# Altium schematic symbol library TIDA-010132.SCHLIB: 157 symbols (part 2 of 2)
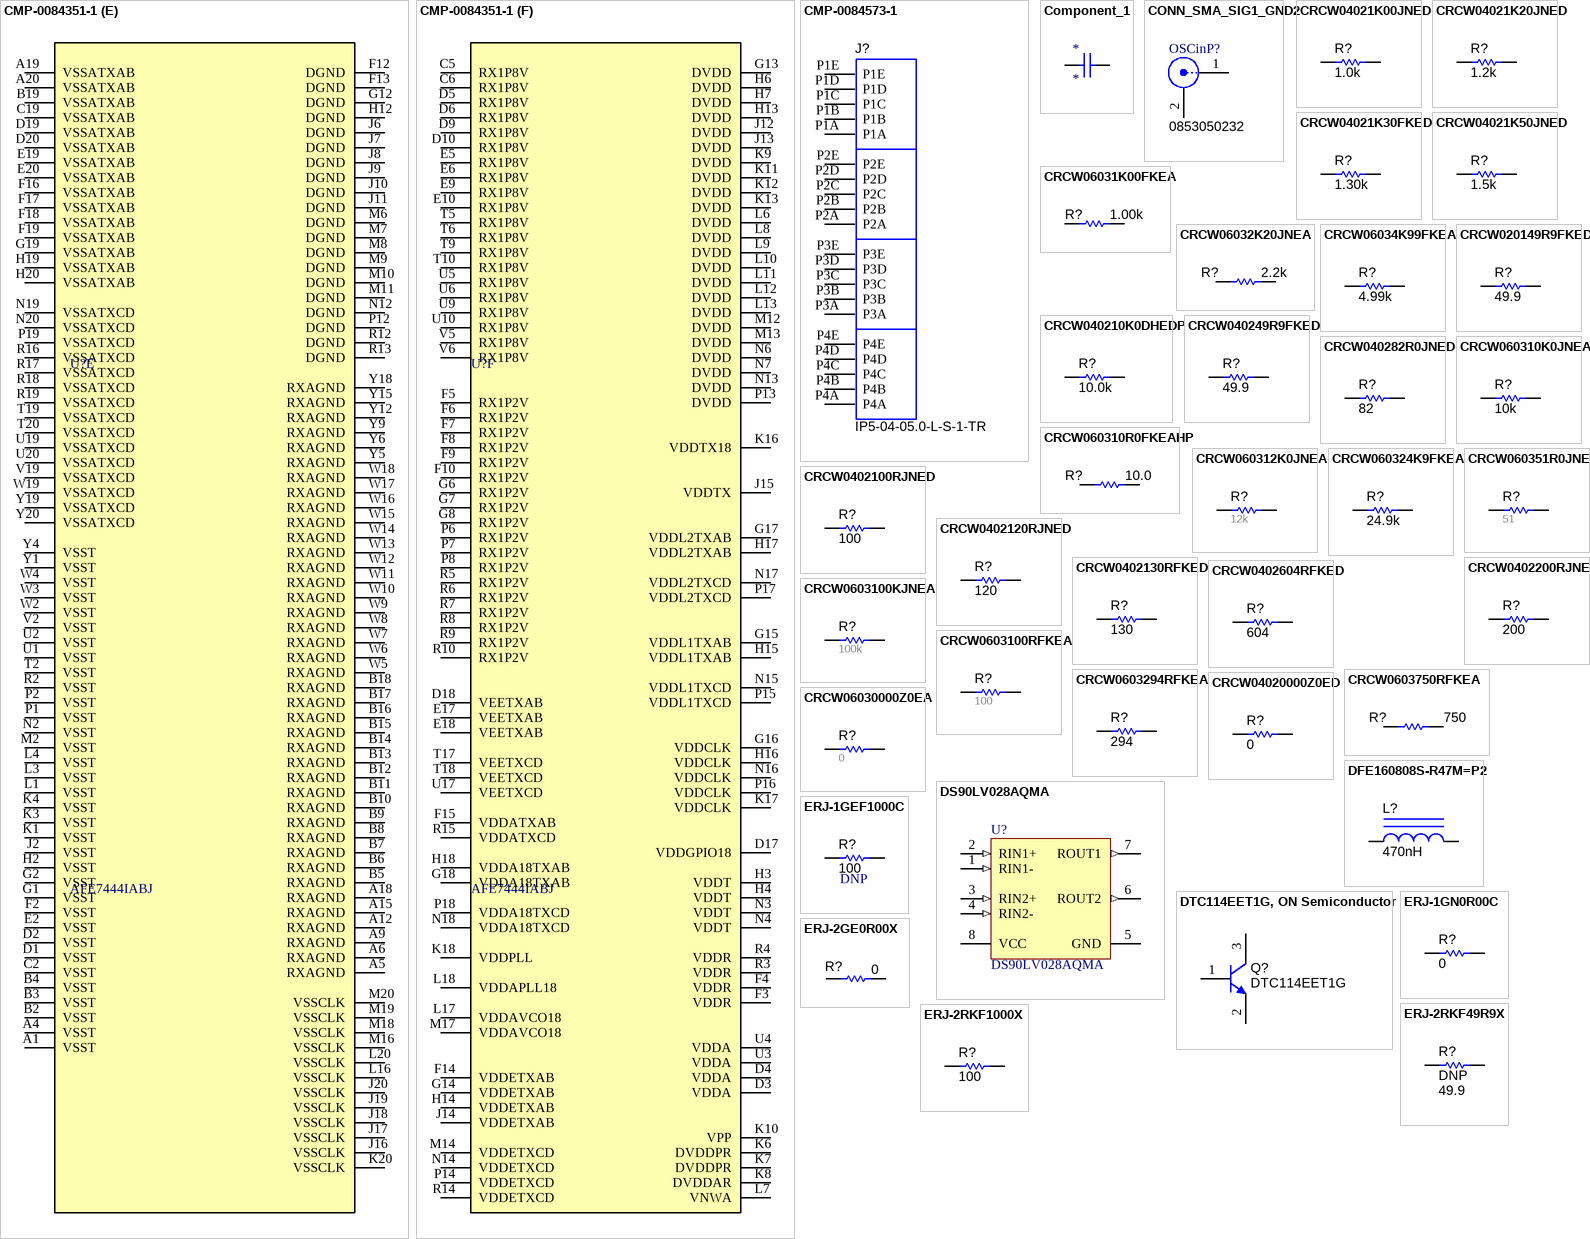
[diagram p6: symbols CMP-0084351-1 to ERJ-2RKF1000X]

## DFE160808S-R47M=P2
designator L?  ValueDisplayed: 470nH  (hidden comment: DFE160808S-R47M=P2)
Inductor, Shielded, Metal Composite, 470 nH, 2.4 A, 0.064 ohm, SMD; Manufacturer: MuRata; Value: 470nH; Ind_H: 470.0E-9; Imax_A: 2.4; Irms: 2.4A @ 40C rise; Isat: 3.1A @ 30% inductance drop; DCR_ohm: 0.064; Value2: 2.4A; SizeAreaWB_mm2: 4.68; SizeArea_mm2: 1.28; SizeX_mm: 1.6; SizeY_mm: 0.8; AEC Category: Q200; AEC Qualified: N; Green_Lifecycle: Not Set; Green_REACh: Incomplete
signal-integrity model Inductor
simulation model Inductor
footprint DFE160808S
pins: 1, 2

## DS90LV028AQMA
designator U?
Automotive LVDS Dual Differential Line Receiver, 8-pin Narrow SOIC; Manufacturer: Texas Instruments; PackageTopMarking: NSZXTT*90LV0*28AQM; PowerWise: N; CompType: Interface IC
footprint M08A_N (SOIC, 8-Leads, Body 4.9x3.9mm, Pitch 1.27mm, IPC Medium Density)
footprint M08A_L (SOIC, 8-Leads, Body 4.9x3.9mm, Pitch 1.27mm, IPC High Density)
footprint M08A_M (SOIC, 8-Leads, Body 4.9x3.9mm, Pitch 1.27mm, IPC Low Density)
pins: 1 RIN1- (in), 2 RIN1+ (in), 3 RIN2+ (in), 4 RIN2- (in), 5 GND (power), 6 ROUT2 (out), 7 ROUT1 (out), 8 VCC (power)

## DTC114EET1G, ON Semiconductor
designator Q?, comment DTC114EET1G
Transistor, NPN, 50 V, 0.1 A, AEC-Q101, SOT-416; Manufacturer: ON Semiconductor; CompType: BJT; PNP: 0; NPN: 1; Vceo_V: 50; Vcesat1_V: 0.25; Value: 50 V; IcRated_A: 0.1; Value1: 0.1 A; HfeMax: 60; TaMin_C: -55; TaMax_C: 150; SizeAreaWB_mm2: 6.76; SizeArea_mm2: 2.56; SizeX_mm: 1.6; SizeZ_mm: 0.95; U/M: EA; AEC Category: Q101; AEC Qualified: Y; Green_Lifecycle: Active; Green_REACh: Passed
footprint SOT-416
pins: 1 B, 2 E, 3 C

## ERJ-1GEF1000C
designator R?  ValueDisplayed: 100  (hidden comment: ERJ-1GEF1000C)
RES, 100, 1%, 0.05 W, 0201; Manufacturer: Panasonic; CompType: Resistor; Value: 100; Value_Code: 100R; Tolerance_%: 1; Power_W: 0.05; Value2: 0.05W; VDC_V: 25; TempCo: 200 ppm/C; SizeArea_mm2: 0.18; SizeX_mm: 0.6; SizeY_mm: 0.3; SizeZ_mm: 0.26; EIA_Code: E96; U/M: EA; AEC Category: Q200
signal-integrity model Resistor
simulation model Resistor
footprint 0201
footprint 0201M
footprint 0201L
footprint 0201_Silk
pins: 1, 2

## ERJ-1GN0R00C
designator R?  ValueDisplayed: 0  (hidden comment: ERJ-1GN0R00C)
RES, 0, 5%, 0.05 W, AEC-Q200 Grade 0, 0201; Manufacturer: Panasonic; CompType: Resistor; Value: 0; Value_Code: 0000; Tolerance_%: 5; Power_W: 0.05; Value2: 0.05W; TempCo: ppm/C; SizeArea_mm2: 0.18; SizeX_mm: 0.6; SizeY_mm: 0.3; SizeZ_mm: 0.26; EIA_Code: E24; U/M: EA; AEC Category: Q200; AEC Qualified: Y
signal-integrity model Resistor
simulation model Resistor
footprint 0201
footprint 0201M
footprint 0201L
footprint 0201_Silk
pins: 1, 2

## ERJ-2GE0R00X
designator R?  ValueDisplayed: 0  (hidden comment: ERJ-2GE0R00X)
RES, 0, 5%, 0.063 W, 0402; Manufacturer: Panasonic; CompType: Resistor; Value: 0; Value_Code: 0000; Tolerance_%: 5; Power_W: 0.063; Value2: 0.063W; VDC_V: 50; TempCo: 600 ppm/C; SizeArea_mm2: 0.5; SizeX_mm: 1; SizeZ_mm: 0.6; EIA_Code: E24; U/M: EA; AEC Category: Q200; Green_Lifecycle: Active; Green_REACh: Passed
signal-integrity model Resistor
simulation model Resistor
footprint 0402
footprint 0402M
footprint 0402L
footprint 0402S
pins: 1, 2

## ERJ-2RKF49R9X
designator R?, comment DNP  ValueDisplayed: 49.9
RES, 49.9, 1%, 0.1 W, AEC-Q200 Grade 0, 0402; PartNumber: ERJ-2RKF49R9X; Manufacturer: Panasonic; CompType: Resistor; Value: 49.9; Value_Code: 49R9; Tolerance_%: 1; Power_W: 0.1; Value2: 0.1W; VDC_V: 50; TempCo: 100 ppm/C; SizeArea_mm2: 0.5; SizeZ_mm: 0.6; EIA_Code: E96; U/M: EA; AEC Category: Q200; AEC Qualified: Y; AEC Grade: 0; Green_Lifecycle: Active; Green_REACh: Passed
signal-integrity model Resistor
simulation model Resistor
footprint 0402
footprint 0402M
footprint 0402L
footprint 0402S
pins: 1, 2

## ERJ-2RKF1000X
designator R?  ValueDisplayed: 100  (hidden comment: ERJ-2RKF1000X)
RES, 100, 1%, 0.1 W, 0402; Manufacturer: Panasonic; CompType: Resistor; Value: 100; Value_Code: 100R; Tolerance_%: 1; Power_W: 0.1; Value2: 0.1W; VDC_V: 50; TempCo: 100 ppm/C; SizeArea_mm2: 0.5; SizeZ_mm: 0.6; EIA_Code: E96; U/M: EA; AEC Category: Q200; Green_Lifecycle: Active; Green_REACh: Passed
signal-integrity model Resistor
simulation model Resistor
footprint 0402
footprint 0402M
footprint 0402L
footprint 0402S
pins: 1, 2

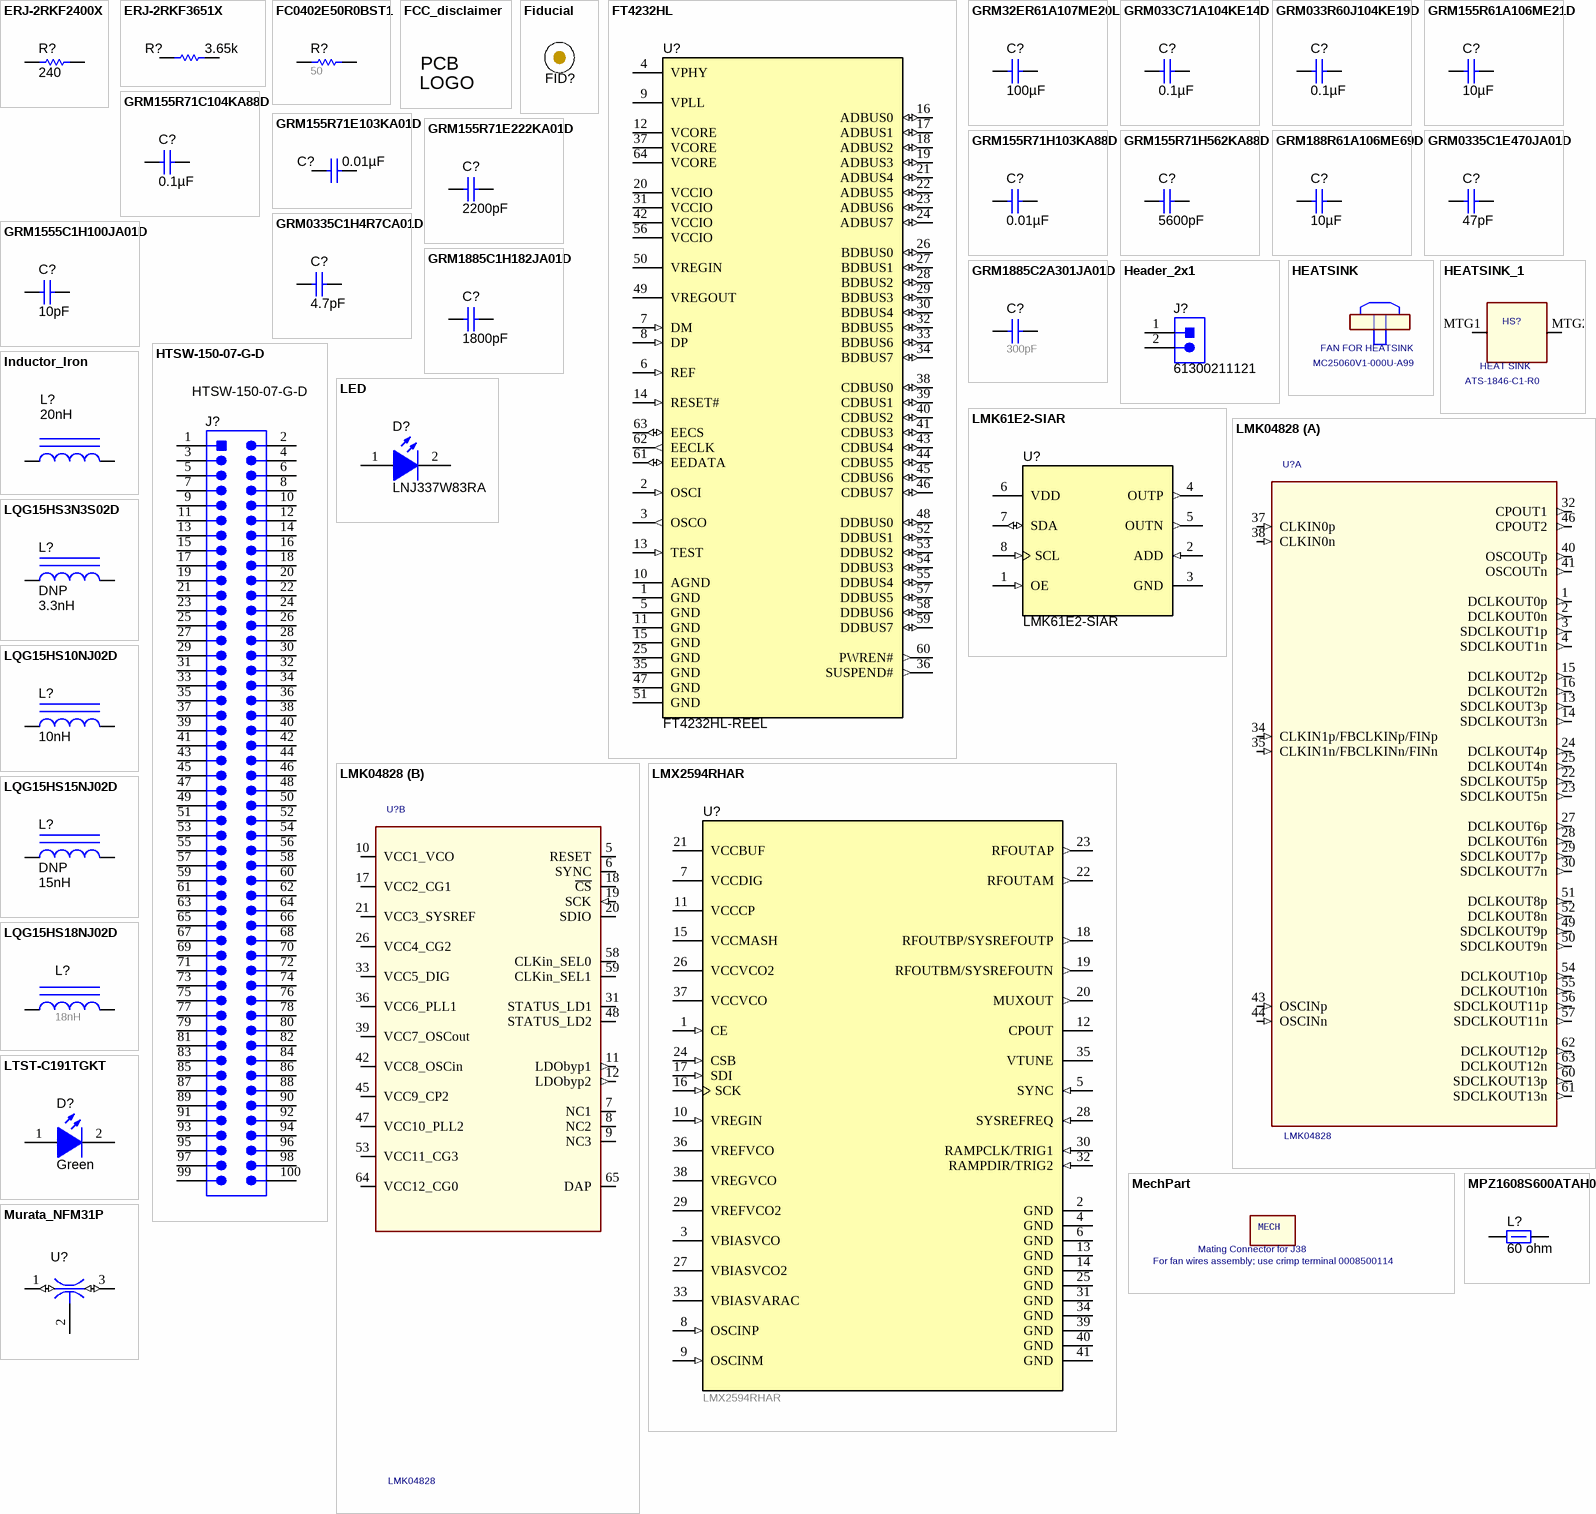
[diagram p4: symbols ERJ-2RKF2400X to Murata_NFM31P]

## ERJ-2RKF2400X
designator R?  ValueDisplayed: 240  (hidden comment: ERJ-2RKF2400X)
RES, 240, 1%, 0.1 W, AEC-Q200 Grade 0, 0402; Manufacturer: Panasonic; CompType: Resistor; Value: 240; Value_Code: 240R; Tolerance_%: 1; Power_W: 0.1; Value2: 0.1W; VDC_V: 50; TempCo: 100 ppm/C; SizeArea_mm2: 0.5; SizeZ_mm: 0.6; U/M: EA; AEC Category: Q200; AEC Qualified: Y; AEC Grade: 0; Green_Lifecycle: Active; Green_REACh: Passed
signal-integrity model Resistor
simulation model Resistor
footprint 0402
footprint 0402M
footprint 0402L
footprint 0402S
pins: 1, 2

## ERJ-2RKF3651X
designator R?  ValueDisplayed: 3.65k  (hidden comment: ERJ-2RKF3651X)
RES, 3.65 k, 1%, 0.1 W, AEC-Q200 Grade 0, 0402; Manufacturer: Panasonic; CompType: Resistor; Value: 3.65k; Res_ohm: 3650; Value_Code: 3k65; Tolerance_%: 1; Power_W: 0.1; Value2: 0.1W; VDC_V: 50; TempCo: 100 ppm/C; SizeArea_mm2: 0.5; SizeZ_mm: 0.6; EIA_Code: E96; U/M: EA; AEC Category: Q200; AEC Qualified: Y; AEC Grade: 0
signal-integrity model Resistor
simulation model Resistor
footprint 0402
footprint 0402M
footprint 0402L
footprint 0402S
pins: 1, 2

## FC0402E50R0BST1
designator R?  ValueDisplayed: 50  (hidden comment: FC0402E50R0BST1)
RES, 50, 0.1%, 0.05 W, 0402; Manufacturer: Vishay-Dale; CompType: Resistor; Value: 50; Value_Code: 50R0; Tolerance_%: 0.1; Power_W: 0.05; Value2: 0.05W; TempCo: 25 ppm/C; U/M: EA; SizeArea_mm2: 0.5; SizeX_mm: 1; SizeZ_mm: 0.6; AEC Category: Q200; AEC Qualified: N
signal-integrity model Resistor
simulation model Resistor
footprint 0402
footprint 0402M
footprint 0402L
footprint 0402S
pins: 1, 2

## FCC_disclaimer
designator Logo?, comment FCC disclaimer  (value not drawn)  (no BOM)
FCC_disclaimer; SymbolCreator: a0412235
footprint FCC_disclaimer
footprint FCC_disclaimer_stacked

## Fiducial
designator FID?  (value not drawn)
Fiducial mark.  There is nothing to buy or mount.; SymbolCreator: codlsc
footprint Fiducial10-30
footprint Fiducial10-20
footprint Fiducial15-30
footprint Fiducial20-40
footprint Fiducial6.4-20

## FT4232HL
designator U?, comment FT4232HL-REEL
Quad High Speed USB to Multipurpose UART/MPSSE IC; Manufacturer: FTDI; SymbolCreator: a0411947
footprint LQFP64_N
footprint LQFP64_M
footprint LQFP64_L
pins: 1 GND (power), 2 OSCI (in), 3 OSCO (out), 4 VPHY (power), 5 GND (power), 6 REF (in), 7 DM (in), 8 DP (in), 9 VPLL (power), 10 AGND (power), 11 GND (power), 12 VCORE (power), 13 TEST (in), 14 RESET# (in), 15 GND (power), 16 ADBUS0 (io), 17 ADBUS1 (io), 18 ADBUS2 (io), 19 ADBUS3 (io), 20 VCCIO (power), 21 ADBUS4 (io), 22 ADBUS5 (io), 23 ADBUS6 (io), 24 ADBUS7 (io), 25 GND (power), 26 BDBUS0 (io), 27 BDBUS1 (io), 28 BDBUS2 (io), 29 BDBUS3 (io), 30 BDBUS4 (io), 31 VCCIO (power), 32 BDBUS5 (io), 33 BDBUS6 (io), 34 BDBUS7 (io), 35 GND (power), 36 SUSPEND# (out), 37 VCORE (power), 38 CDBUS0 (io), 39 CDBUS1 (io), 40 CDBUS2 (io), 41 CDBUS3 (io), 42 VCCIO (power), 43 CDBUS4 (io), 44 CDBUS5 (io), 45 CDBUS6 (io), 46 CDBUS7 (io), 47 GND (power), 48 DDBUS0 (io), 49 VREGOUT (power), 50 VREGIN (power), 51 GND (power), 52 DDBUS1 (io), 53 DDBUS2 (io), 54 DDBUS3 (io), 55 DDBUS4 (io), 56 VCCIO (power), 57 DDBUS5 (io), 58 DDBUS6 (io), 59 DDBUS7 (io), 60 PWREN# (out), 61 EEDATA (io), 62 EECLK (out), 63 EECS (io), 64 VCORE (power)

## GRM32ER61A107ME20L
designator C?  ValueDisplayed: 100µF  (hidden comment: GRM32ER61A107ME20L)
CAP, CERM, 100 µF, 10 V, +/- 20%, X5R, 1210; Manufacturer: MuRata; Polarized: N; CompType: Capacitor; Value: 100uF; U/M: EA; Cap_F: 0.0001; Tolerance_%: 20; Value1: Unknown; VDC_V: 10; Value2: 10V; TaMin_C: -55; TaMax_C: 85; Cap_Case: 1210; SizeArea_mm2: 8; SizeAreaWB_mm2: 14.7; SizeX_mm: 3.2; SizeY_mm: 2.5; SizeZ_mm: 2.7; AEC Category: Q200
signal-integrity model Cap
simulation model Cap
footprint 1210_270
footprint 1210_270M
footprint 1210_270L
pins: 1, 2

## GRM033C71A104KE14D
designator C?  ValueDisplayed: 0.1µF  (hidden comment: GRM033C71A104KE14D)
CAP, CERM, 0.1 µF, 10 V,+/- 10%, X7S, 0201; Manufacturer: MuRata; Polarized: N; CompType: Capacitor; Value: 0.1uF; U/M: EA; Cap_F: 0.0000001; Tolerance_%: 10; Value1: Unknown; Value2: 10V; TaMin_C: -55; TaMax_C: 125; Cap_Case: 0201; SizeArea_mm2: 0.18; SizeAreaWB_mm2: 2.08; SizeX_mm: 0.6; SizeY_mm: 0.3; SizeZ_mm: 0.26; AEC Category: Q200
signal-integrity model Cap
simulation model Cap
footprint 0201
footprint 0201M
footprint 0201L
footprint 0201_Silk
pins: 1, 2

## GRM033R60J104KE19D
designator C?  ValueDisplayed: 0.1µF  (hidden comment: GRM033R60J104KE19D)
CAP, CERM, 0.1 µF, 6.3 V, +/- 10%, X5R, 0201; Manufacturer: MuRata; Polarized: N; CompType: Capacitor; Value: 0.1uF; U/M: EA; Cap_F: 0.0000001; Tolerance_%: 10; Value1: Unknown; VDC_V: 6.3; Value2: 6.3V; TaMin_C: -55; TaMax_C: 85; Cap_Case: 0201; SizeArea_mm2: 0.18; SizeAreaWB_mm2: 2.08; SizeX_mm: 0.6; SizeY_mm: 0.3; SizeZ_mm: 0.33; AEC Category: Q200
signal-integrity model Cap
simulation model Cap
footprint 0201_033
footprint 0201_033M
footprint 0201_033L
pins: 1, 2

## GRM155R61A106ME21D
designator C?  ValueDisplayed: 10µF  (hidden comment: GRM155R61A106ME21D)
CAP, CERM, 10 µF, 10 V,+/- 20%, X5R, 0402; Manufacturer: MuRata; Polarized: N; CompType: Capacitor; Value: 10uF; U/M: EA; Cap_F: 0.00001; Tolerance_%: 20; VDC_V: 10; Value2: 10V; TaMin_C: -55; TaMax_C: 85; Cap_Case: 0402; SizeArea_mm2: 0.5; SizeAreaWB_mm2: 3; SizeX_mm: 1; SizeZ_mm: 0.7; AEC Category: Q200; Green_Lifecycle: Not Set; Green_REACh: Incomplete
signal-integrity model Cap
simulation model Cap
footprint 0402_070
pins: 1, 2

## GRM155R71C104KA88D
designator C?  ValueDisplayed: 0.1µF  (hidden comment: GRM155R71C104KA88D)
CAP, CERM, 0.1 µF, 16 V, +/- 10%, X7R, 0402; Manufacturer: MuRata; Polarized: N; CompType: Capacitor; Value: 0.1uF; U/M: EA; Cap_F: 0.0000001; Tolerance_%: 10; Value1: Unknown; VDC_V: 16; Value2: 16V; TaMin_C: -55; TaMax_C: 125; Cap_Case: 0402; SizeArea_mm2: 0.5; SizeAreaWB_mm2: 3; SizeX_mm: 1; SizeZ_mm: 0.6; AEC Category: Q200
signal-integrity model Cap
simulation model Cap
footprint 0402
footprint 0402M
footprint 0402L
footprint 0402S
pins: 1, 2

## GRM155R71E103KA01D
designator C?  ValueDisplayed: 0.01µF  (hidden comment: GRM155R71E103KA01D)
CAP, CERM, 0.01 µF, 25 V, +/- 10%, X7R, 0402; Manufacturer: MuRata; Polarized: N; CompType: Capacitor; Value: 0.01uF; U/M: EA; Cap_F: 0.00000001; Tolerance_%: 10; Value1: Unknown; VDC_V: 25; Value2: 25V; TaMin_C: -55; TaMax_C: 125; Cap_Case: 0402; SizeArea_mm2: 0.5; SizeAreaWB_mm2: 3; SizeX_mm: 1; SizeZ_mm: 0.6; AEC Category: Q200
signal-integrity model Cap
simulation model Cap
footprint 0402
footprint 0402M
footprint 0402L
footprint 0402S
pins: 1, 2

## GRM155R71E222KA01D
designator C?  ValueDisplayed: 2200pF  (hidden comment: GRM155R71E222KA01D)
CAP, CERM, 2200 pF, 25 V, +/- 10%, X7R, 0402; Manufacturer: MuRata; Polarized: N; CompType: Capacitor; Value: 2200pF; U/M: EA; Cap_F: 0.0000000022; Tolerance_%: 10; Value1: Unknown; VDC_V: 25; Value2: 25V; TaMin_C: -55; TaMax_C: 125; Cap_Case: 0402; SizeArea_mm2: 0.5; SizeAreaWB_mm2: 3; SizeX_mm: 1; SizeZ_mm: 0.6; AEC Category: Q200
signal-integrity model Cap
simulation model Cap
footprint 0402
footprint 0402M
footprint 0402L
footprint 0402S
pins: 1, 2

## GRM155R71H103KA88D
designator C?  ValueDisplayed: 0.01µF  (hidden comment: GRM155R71H103KA88D)
CAP, CERM, 0.01 µF, 50 V,+/- 10%, X7R, 0402; Manufacturer: MuRata; Polarized: N; CompType: Capacitor; Value: 0.01uF; U/M: EA; Cap_F: 0.00000001; Tolerance_%: 10; Value1: Unknown; VDC_V: 50; Value2: 50V; TaMin_C: -55; TaMax_C: 125; Cap_Case: 0402; SizeArea_mm2: 0.5; SizeAreaWB_mm2: 3; SizeX_mm: 1; SizeZ_mm: 0.6; AEC Category: Q200; Green_Lifecycle: Active; Green_REACh: Passed
signal-integrity model Cap
simulation model Cap
footprint 0402
footprint 0402M
footprint 0402L
footprint 0402S
pins: 1, 2

## GRM155R71H562KA88D
designator C?  ValueDisplayed: 5600pF  (hidden comment: GRM155R71H562KA88D)
CAP, CERM, 5600 pF, 50 V,+/- 10%, X7R, 0402; Manufacturer: MuRata; Polarized: N; CompType: Capacitor; Value: 5600pF; U/M: EA; Cap_F: 0.0000000056; Tolerance_%: 10; Value1: Unknown; VDC_V: 50; Value2: 50V; TaMin_C: -55; TaMax_C: 125; Cap_Case: 0402; SizeArea_mm2: 0.5; SizeAreaWB_mm2: 3; SizeX_mm: 1; SizeZ_mm: 0.6; AEC Category: Q200; Green_Lifecycle: Active; Green_REACh: Passed
signal-integrity model Cap
simulation model Cap
footprint 0402
footprint 0402M
footprint 0402L
footprint 0402S
pins: 1, 2

## GRM188R61A106ME69D
designator C?  ValueDisplayed: 10µF  (hidden comment: GRM188R61A106ME69D)
CAP, CERM, 10 µF, 10 V, +/- 20%, X5R, 0603; Manufacturer: MuRata; Polarized: N; CompType: Capacitor; Value: 10uF; U/M: EA; Cap_F: 0.00001; Tolerance_%: 20; Value1: Unknown; VDC_V: 10; Value2: 10V; TaMin_C: -55; TaMax_C: 85; Cap_Case: 0603; SizeArea_mm2: 1.28; SizeAreaWB_mm2: 4.68; SizeX_mm: 1.6; SizeY_mm: 0.8; SizeZ_mm: 1; AEC Category: Q200
signal-integrity model Cap
simulation model Cap
footprint 0603
footprint 0603M
footprint 0603L
footprint 0603_HV
footprint 0603S
pins: 1, 2

## GRM0335C1E470JA01D
designator C?  ValueDisplayed: 47pF  (hidden comment: GRM0335C1E470JA01D)
CAP, CERM, 47 pF, 25 V, +/- 5%, C0G/NP0, 0201; Manufacturer: MuRata; Polarized: N; CompType: Capacitor; Value: 47pF; U/M: EA; Cap_F: 0.000000000047; Tolerance_%: 5; Value1: Unknown; VDC_V: 25; Value2: 25V; TaMin_C: -55; TaMax_C: 125; Cap_Case: 0201; SizeArea_mm2: 0.18; SizeAreaWB_mm2: 2.08; SizeX_mm: 0.6; SizeY_mm: 0.3; SizeZ_mm: 0.33; AEC Category: Q200
signal-integrity model Cap
simulation model Cap
footprint 0201_033
footprint 0201_033M
footprint 0201_033L
pins: 1, 2

## GRM0335C1H4R7CA01D
designator C?  ValueDisplayed: 4.7pF  (hidden comment: GRM0335C1H4R7CA01D)
CAP, CERM, 4.7 pF, 50 V,+/- 5%, C0G/NP0, 0201; Manufacturer: MuRata; Polarized: N; CompType: Capacitor; Value: 4.7pF; U/M: EA; Cap_F: 0.0000000000047; Tolerance_%: 5; Value1: Unknown; VDC_V: 50; Value2: 50V; TaMin_C: -55; TaMax_C: 125; Cap_Case: 0201; SizeArea_mm2: 0.18; SizeAreaWB_mm2: 2.08; SizeX_mm: 0.6; SizeY_mm: 0.3; SizeZ_mm: 0.26; AEC Category: Q200
signal-integrity model Cap
simulation model Cap
footprint 0201
footprint 0201M
footprint 0201L
footprint 0201_Silk
pins: 1, 2

## GRM1555C1H100JA01D
designator C?  ValueDisplayed: 10pF  (hidden comment: GRM1555C1H100JA01D)
CAP, CERM, 10 pF, 50 V, +/- 5%, C0G/NP0, 0402; Manufacturer: MuRata; Polarized: N; CompType: Capacitor; Value: 10pF; U/M: EA; Cap_F: 0.00000000001; Tolerance_%: 5; Value1: Unknown; VDC_V: 50; Value2: 50V; TaMin_C: -55; TaMax_C: 125; Cap_Case: 0402; SizeArea_mm2: 0.5; SizeAreaWB_mm2: 3; SizeX_mm: 1; SizeZ_mm: 0.6; AEC Category: Q200
signal-integrity model Cap
simulation model Cap
footprint 0402
footprint 0402M
footprint 0402L
footprint 0402S
pins: 1, 2

## GRM1885C1H182JA01D
designator C?  ValueDisplayed: 1800pF  (hidden comment: GRM1885C1H182JA01D)
CAP, CERM, 1800 pF, 50 V, +/- 5%, C0G/NP0, 0603; Manufacturer: MuRata; Cap_Case: 0603; Polarized: N; TaMax_C: 125; TaMin_C: -55; Tolerance_%: 5; VDC_V: 50; Cap_F: 0.0000000018; CompType: Capacitor; Value: 1800pF; Value1: Unknown; Value2: 50V; U/M: EA; SizeArea_mm2: 1.28; SizeAreaWB_mm2: 4.68; SizeX_mm: 1.6; SizeY_mm: 0.8; SizeZ_mm: 1; AEC Category: Q200
signal-integrity model Cap
simulation model Cap
footprint 0603
footprint 0603M
footprint 0603L
footprint 0603_HV
footprint 0603S
pins: 1, 2

## GRM1885C2A301JA01D
designator C?  ValueDisplayed: 300pF  (hidden comment: GRM1885C2A301JA01D)
CAP, CERM, 300pF, 100V, +/-5%, C0G/NP0, 0603; Manufacturer: MuRata; Cap_Case: 0603; Polarized: N; TaMax_C: 125; TaMin_C: -55; Tolerance_%: 5; VDC_V: 100; Cap_F: 0.0000000003; CompType: Capacitor; Value1: Unknown; U/M: EA
signal-integrity model Cap
simulation model Cap
footprint 0603
footprint 0603M
footprint 0603L
footprint 0603_HV
footprint 0603S
pins: 1, 2

## Header_2x1
designator J?, comment 61300211121
Header, 2.54 mm, 2x1, Gold, TH; Manufacturer: Wurth Elektronik; CNHeader: TRUE; Green_Lifecycle: Active; Green_REACh: Passed; CT: FALSE
footprint WURTH_61300211121 (Header, 2.54mm, 2x1, TH)
pins: 1, 2
1 alternate drawing of the same symbol

## HEATSINK
designator Z_FANHEATSINK?, comment FAN FOR HEATSINK  Part Number: MC25060V1-000U-A99  (mechanical)
FAN AXIAL 25X6.9MM 5VDC WIRE; Manufacturer: SUNON

## HEATSINK_1
designator HS?, comment HEAT SINK  Part Number: ATS-1846-C1-R0
1/2 BRICK HEATSINK 58X61X11.4MM; Manufacturer: Advanced Thermal Solutions
footprint HEATSINK_27X27MM_ATS
footprint HEATSINK_27X27mm_ATS
pins: MTG1, MTG2

## HTSW-150-07-G-D
designator J?
Header, 2.54mm, 50x2, Gold, TH; Manufacturer: Samtec; SymbolCreator: a0799628; Pitch_mm: 2.54; Gender: Male; Shrouded: N; Row_Count: 2; Cert_CSA: Y; Green_Lifecycle: Active; Green_REACh: Passed
footprint Samtec_HTSW-150-07-x-D
pins: 1, 2, 3, 4, 5, 6, 7, 8, 9, 10, 11, 12, 13, 14, 15, 16, 17, 18, 19, 20, 21, 22, 23, 24, 25, 26, 27, 28, 29, 30, 31, 32, 33, 34, 35, 36, 37, 38, 39, 40, 41, 42, 43, 44, 45, 46, 47, 48, 49, 50, 51, 52, 53, 54, 55, 56, 57, 58, 59, 60, 61, 62, 63, 64, 65, 66, 67, 68, 69, 70, 71, 72, 73, 74, 75, 76, 77, 78, 79, 80, 81, 82, 83, 84, 85, 86, 87, 88, 89, 90, 91, 92, 93, 94, 95, 96, 97, 98, 99, 100

## Inductor_Iron
designator L?, comment ValueDisplayed: 20nH  (hidden comment: LQG15WZ20NH02D)
Inductor, Multilayer, Air Core, 20 nH, 0.26 A, 1.1 ohm, AEC-Q200 Grade 1, SMD; Manufacturer: MuRata; Irms: 0.26A @ 25C rise; SizeAreaWB_mm2: 3.2; DCR_ohm: 1.1; Value1: 1.1 ohm; Value: 20nH; Imax_A: 2.6dA; SizeZ_mm: 0.6; SizeX_mm: 1; Value2: 0.26A; AEC Qualified: Y; AEC Category: Q200
footprint LQG15WZ_02 (MuRata recommended land pattern)
footprint 0402 (0402 from SM-752 data)
footprint 0402M (0402 from SM-752 data)
footprint 0402L (0402 from SM-752 data)
footprint 0402S (Based on C0402S footprint from PADS legacy)
pins: 1, 2

## LED
designator D?, comment LNJ337W83RA
LED, Green, SMD; Manufacturer: Panasonic; Io_A: 5mA; Vr_V: 4V; Tjmax_C: 85°C; Value1: W; U/M: EA; Ir_A: 10µA; Vf_V: 1.95V
footprint LNJx37x8_Green (SMD, 2-Leads, Body 1.6x0.8mm)
pins: 1 A, 2 K

## LMK61E2-SIAR
designator U?
Ultra-Low Jitter Programmable Oscillator with Internal EEPROM, SIA0008B; Alternate PartNumber: LMK61E2-SIAT; Manufacturer: Texas Instruments; SymbolCreator: Altium; CompType: IC; U/M: EA
footprint SIA0008B
pins: 1 OE (in), 2 ADD (in), 3 GND (power), 4 OUTP (out), 5 OUTN (out), 6 VDD (power), 7 SDA (io), 8 SCL (in)

## LMK04828
designator U?
LMK04828BISQE/NOPB; Manufacturer: Texas Instruments
footprint NKD0064A (QFN, 64-Leads, Body 9x9mm, Pitch 0.5mm)
part A pins: 1 DCLKOUT0p (out), 2 DCLKOUT0n (out), 3 SDCLKOUT1p (out), 4 SDCLKOUT1n (out), 13 SDCLKOUT3p (out), 14 SDCLKOUT3n (out), 15 DCLKOUT2p (out), 16 DCLKOUT2n (out), 22 SDCLKOUT5p (out), 23 SDCLKOUT5n (out), 24 DCLKOUT4p (out), 25 DCLKOUT4n (out), 27 DCLKOUT6p (out), 28 DCLKOUT6n (out), 29 SDCLKOUT7p (out), 30 SDCLKOUT7n (out), 32 CPOUT1 (out), 34 CLKIN1p/FBCLKINp/FINp (in), 35 CLKIN1n/FBCLKINn/FINn (in), 37 CLKIN0p (in), 38 CLKIN0n (in), 40 OSCOUTp (out), 41 OSCOUTn (out), 43 OSCINp (in), 44 OSCINn (in), 46 CPOUT2 (out), 49 SDCLKOUT9p (out), 50 SDCLKOUT9n (out), 51 DCLKOUT8p (out), 52 DCLKOUT8n (out), 54 DCLKOUT10p (out), 55 DCLKOUT10n (out), 56 SDCLKOUT11p (out), 57 SDCLKOUT11n (out), 60 SDCLKOUT13p (out), 61 SDCLKOUT13n (out), 62 DCLKOUT12p (out), 63 DCLKOUT12n (out)
part B pins: 5 RESET (io), 6 SYNC (io), 7 NC1, 8 NC2, 9 NC3, 10 VCC1_VCO (power), 11 LDObyp1 (out), 12 LDObyp2 (out), 17 VCC2_CG1 (power), 18 ~{CS} (io), 19 SCK (in), 20 SDIO (io), 21 VCC3_SYSREF (power), 26 VCC4_CG2 (power), 31 STATUS_LD1 (io), 33 VCC5_DIG (power), 36 VCC6_PLL1 (power), 39 VCC7_OSCout (power), 42 VCC8_OSCin (power), 45 VCC9_CP2 (power), 47 VCC10_PLL2 (power), 48 STATUS_LD2 (io), 53 VCC11_CG3 (power), 58 CLKin_SEL0 (io), 59 CLKin_SEL1 (io), 64 VCC12_CG0 (power), 65 DAP (power)

## LMX2594RHAR
designator U?
High Performance, Wideband PLLatinum RF Synthesizer, RHA0040A (VQFN-40); Alternate PartNumber: LMX2594RHAT; Manufacturer: Texas Instruments; SymbolCreator: Altium; SizeArea_mm2: 36; SizeAreaWB_mm2: 64; SizeX_mm: 6; SizeZ_mm: 1; CompType: IC; U/M: EA
footprint RHA0040A (QFN, 40-Leads, Body 6x6mm, Pitch 0.5mm, Thermal Pad 4.6x4.6mm, TI Recommended)
footprint RHA0040A_NV
footprint RHA0040C
pins: 1 CE (in), 2 GND (power), 3 VBIASVCO, 4 GND (power), 5 SYNC (in), 6 GND (power), 7 VCCDIG (power), 8 OSCINP (in), 9 OSCINM (in), 10 VREGIN (in), 11 VCCCP (power), 12 CPOUT, 13 GND (power), 14 GND (power), 15 VCCMASH (power), 16 SCK (in), 17 SDI (in), 18 RFOUTBP/SYSREFOUTP (out), 19 RFOUTBM/SYSREFOUTN (out), 20 MUXOUT (out), 21 VCCBUF (power), 22 RFOUTAM (out), 23 RFOUTAP (out), 24 CSB (in), 25 GND (power), 26 VCCVCO2 (power), 27 VBIASVCO2, 28 SYSREFREQ (in), 29 VREFVCO2, 30 RAMPCLK/TRIG1 (in), 31 GND (power), 32 RAMPDIR/TRIG2 (in), 33 VBIASVARAC, 34 GND (power), 35 VTUNE, 36 VREFVCO, 37 VCCVCO (power), 38 VREGVCO, 39 GND (power), 40 GND (power), 41 GND (power)

## LQG15HS3N3S02D
designator L?, comment DNP  ValueDisplayed: 3.3nH
Inductor, Multilayer, Air Core, 3.3 nH, 0.3 A, 0.17 ohm, SMD; PartNumber: LQG15HS3N3S02D; Manufacturer: MuRata; Value: 3.3nH; Ind_H: 3.3E-9; Imax_A: 0.3; Irms: 0.3A @ C rise; Isat: 0.3A @ % inductance drop; DCR_ohm: 0.17; Value2: 0.3A; SizeAreaWB_mm2: 3; SizeArea_mm2: 0.5; SizeX_mm: 1; SizeZ_mm: 0.55; AEC Category: Q200; Green_Lifecycle: Active; Green_REACh: Passed
signal-integrity model Inductor
simulation model Inductor
footprint IND_LQG15H
pins: 1, 2

## LQG15HS10NJ02D
designator L?  ValueDisplayed: 10nH  (hidden comment: LQG15HS10NJ02D)
Inductor, Multilayer, Air Core, 10 nH, 0.3 A, 0.26 ohm, SMD; Manufacturer: MuRata; Value: 10nH; Ind_H: 10.0E-9; Imax_A: 0.3; Irms: 0.3A @ C rise; Isat: 0.3A @ % inductance drop; DCR_ohm: 0.26; Value2: 0.3A; SizeAreaWB_mm2: 3; SizeArea_mm2: 0.5; SizeX_mm: 1; SizeZ_mm: 0.55; AEC Category: Q200; Green_Lifecycle: Active; Green_REACh: Passed
signal-integrity model Inductor
simulation model Inductor
footprint IND_LQG15H
pins: 1, 2

## LQG15HS15NJ02D
designator L?, comment DNP  ValueDisplayed: 15nH
Inductor, Multilayer, Air Core, 15 nH, 0.3 A, 0.32 ohm, SMD; PartNumber: LQG15HS15NJ02D; Manufacturer: MuRata; Value: 15nH; Ind_H: 15.0E-9; Imax_A: 0.3; Irms: 0.3A @ C rise; Isat: 0.3A @ % inductance drop; DCR_ohm: 0.32; Value2: 0.3A; SizeAreaWB_mm2: 3; SizeArea_mm2: 0.5; SizeX_mm: 1; SizeZ_mm: 0.55; AEC Category: Q200; Green_Lifecycle: Active; Green_REACh: Passed
signal-integrity model Inductor
simulation model Inductor
footprint IND_LQG15H
pins: 1, 2

## LQG15HS18NJ02D
designator L?  ValueDisplayed: 18nH  (hidden comment: LQG15HS18NJ02D)
Inductor, Multilayer, Air Core, 18 nH, 0.3 A, 0.36 ohm, SMD; Manufacturer: MuRata; Value: 18nH; Ind_H: 18.0E-9; Imax_A: 0.3; Irms: 0.3A @ C rise; Isat: 0.3A @ % inductance drop; DCR_ohm: 0.36; Value2: 0.3A; AEC Category: Q200
signal-integrity model Inductor
simulation model Inductor
footprint IND_LQG15H
pins: 1, 2

## LTST-C191TGKT
designator D?  value Green  (hidden comment: LTST-C191TGKT)
LED, Green, SMD; Manufacturer: Lite-On; Type: InGaN; Vf_V: 3.2; Value2: 3.2V; Io_A: 0.02; Value1: W; U/M: EA
signal-integrity model Diode
footprint LTST-C191_Green
pins: 1 A, 2 K

## MechPart
designator CONN HOUS ?, comment Mating Connector for J38  Note: For fan wires assembly; use crimp terminal 0008500114  (mechanical)
CONN HOUS 2POS .100 W/RAMP/RIB; Manufacturer: Molex

## MPZ1608S600ATAH0
designator L?  ValueDisplayed: 60 ohm  (hidden comment: MPZ1608S600ATAH0)
Ferrite Bead, 60 ohm @ 100 MHz, 3.5 A, 0603; Manufacturer: TDK; Value: 60 ohm; Imax_A: 3.5; DCR_ohm: 0.02; Value1: 0.02 ohm; Value2: 3.5A; SizeAreaWB_mm2: 4.68; SizeArea_mm2: 1.28; SizeX_mm: 1.6; SizeY_mm: 0.8; SizeZ_mm: 1; ZTyp@100MHz_Ohm: 60; Green_Lifecycle: Active; Green_REACh: Passed
footprint 0603
footprint 0603M
footprint 0603L
footprint 0603_HV
footprint 0603S
pins: 1, 2

## Murata_NFM31P
designator U?, comment NFM31PC276B0J3L  (value not drawn)
FILTER LC HIGH FREQ 27uF 1206; Manufacturer: MuRata
footprint Murata_NFM31P (SMD, 3-Leads, Body 3.2x1.6mm)
pins: 1 (io), 2 (power), 3 (io)

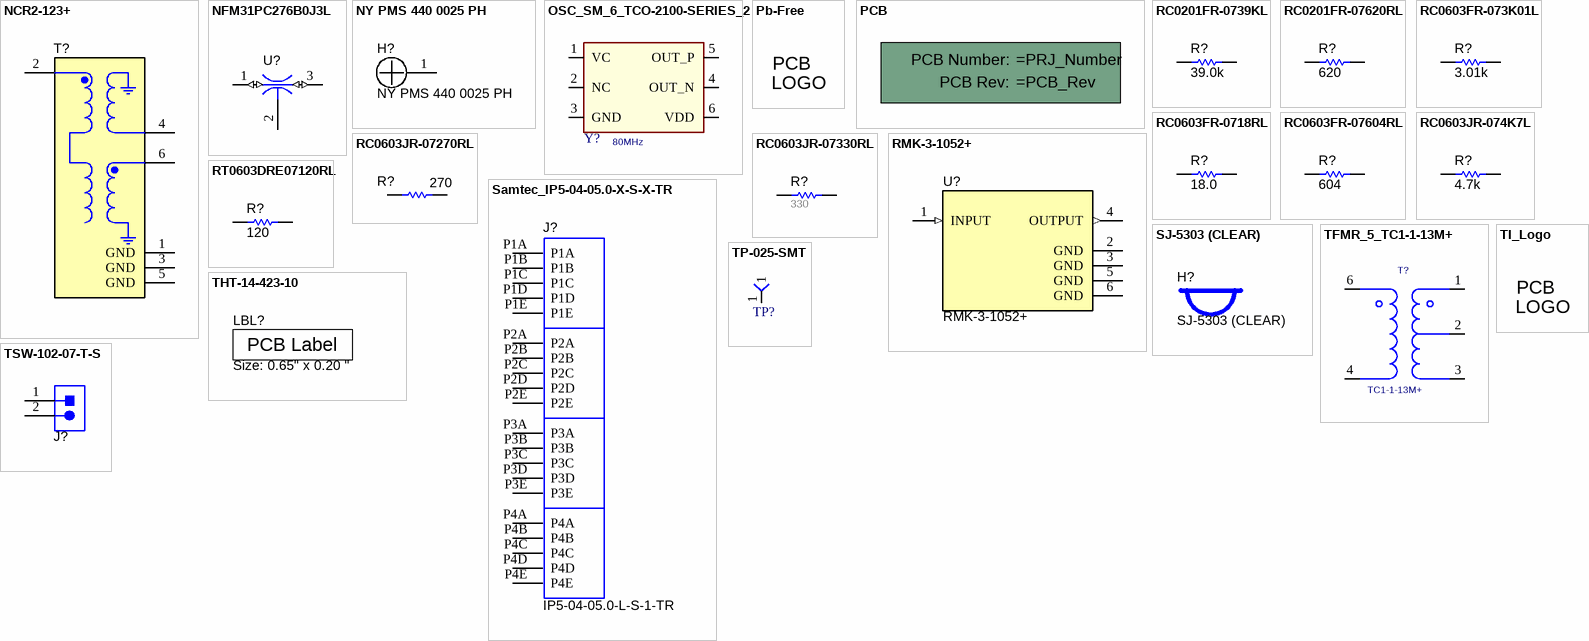
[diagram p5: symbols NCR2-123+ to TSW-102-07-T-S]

## NCR2-123+
designator T?, comment NCR2-113+  (value not drawn)
RF Transformer, 50 Ohm, 3W, SMT; Manufacturer: Minicircuits; SymbolCreator: Altium; SizeAreaWB_mm2: 10.5049; SizeArea_mm2: 5.0049; SizeX_mm: 2.01; SizeY_mm: 2.49; SizeZ_mm: 0.89
footprint MNC_NF1846-1
pins: 1 GND, 2, 3 GND, 4, 5 GND, 6

## NFM31PC276B0J3L
designator U?  (value not drawn)
FILTER LC HIGH FREQ 27uF 1206; Manufacturer: MuRata; SymbolCreator: Altium
footprint Murata_NFM31P
pins: 1 (io), 2 (power), 3 (io)

## NY PMS 440 0025 PH
designator H?
Machine Screw, Round, #4-40 x 1/4, Nylon, Philips panhead; Manufacturer: B&F Fastener Supply; CompType: Hardware; SymbolCreator: codlsc; U/M: EA; Green_Lifecycle: Not Set; Green_REACh: Incomplete
footprint NY PMS 440 0025 PH
footprint NY PMS 440 0025 PH_3Donly
pins: 1

## OSC_SM_6_TCO-2100-SERIES_2
designator Y?, comment 80MHz
Mfr_Name: EPSON TOYOCOM; Mfr_Part_Number: TCO-2111-AA 614.4000MHZ
footprint VCXO_6_CUSTOM
pins: 1 VC (power), 2 NC, 3 GND (power), 4 OUT_N, 5 OUT_P, 6 VDD (power)

## Pb-Free
designator Logo?, comment Pb-Free Symbol  (value not drawn)  (no BOM)
SymbolCreator: a0412235
footprint Pb-Free_Overlay_Medium
footprint Pb-Free_Overlay_Small

## PCB
designator !PCB?, comment Printed Circuit Board  (value not drawn)  (mechanical)
Manufacturer: Any; SymbolCreator: a0412235; CompType: PCB
1 alternate drawing of the same symbol

## RC0201FR-0739KL
designator R?  ValueDisplayed: 39.0k  (hidden comment: RC0201FR-0739KL)
RES, 39.0 k, 1%, 0.05 W, 0201; Manufacturer: Yageo America; CompType: Resistor; Value: 39.0k; Res_ohm: 39000; Value_Code: 39k0; Tolerance_%: 1; Power_W: 0.05; Value2: 0.05W; VDC_V: 25; TempCo: 200 ppm/C; SizeArea_mm2: 0.18; SizeX_mm: 0.6; SizeY_mm: 0.3; SizeZ_mm: 0.26; U/M: EA; AEC Category: Q200; AEC Qualified: N
signal-integrity model Resistor
simulation model Resistor
footprint 0201
footprint 0201M
footprint 0201L
footprint 0201_Silk
pins: 1, 2

## RC0201FR-07620RL
designator R?  ValueDisplayed: 620  (hidden comment: RC0201FR-07620RL)
RES, 620, 1%, 0.05 W, 0201; Manufacturer: Yageo America; CompType: Resistor; Value: 620; Value_Code: 620R; Tolerance_%: 1; Power_W: 0.05; Value2: 0.05W; VDC_V: 25; TempCo: 200 ppm/C; SizeArea_mm2: 0.18; SizeX_mm: 0.6; SizeY_mm: 0.3; SizeZ_mm: 0.26; U/M: EA; AEC Category: Q200; AEC Qualified: N
signal-integrity model Resistor
simulation model Resistor
footprint 0201
footprint 0201M
footprint 0201L
footprint 0201_Silk
pins: 1, 2

## RC0603FR-073K01L
designator R?  ValueDisplayed: 3.01k  (hidden comment: RC0603FR-073K01L)
RES, 3.01 k, 1%, 0.1 W, 0603; Manufacturer: Yageo America; CompType: Resistor; Value: 3.01k; Res_ohm: 3010; Value_Code: 3k01; Tolerance_%: 1; Power_W: 0.1; Value2: 0.1W; VDC_V: 150; TempCo: 200 ppm/C; SizeArea_mm2: 1.28; SizeX_mm: 1.6; SizeY_mm: 0.8; EIA_Code: E96; U/M: EA; AEC Category: Q200; Green_Lifecycle: Active; Green_REACh: Passed
signal-integrity model Resistor
simulation model Resistor
footprint 0603
footprint 0603M
footprint 0603L
footprint 0603_HV
footprint 0603S
pins: 1, 2

## RC0603FR-0718RL
designator R?  ValueDisplayed: 18.0  (hidden comment: RC0603FR-0718RL)
RES, 18.0, 1%, 0.1 W, 0603; Manufacturer: Yageo America; CompType: Resistor; Value: 18.0; Res_ohm: 18; Value_Code: 18R0; Tolerance_%: 1; Power_W: 0.1; Value2: 0.1W; VDC_V: 150; TempCo: 200 ppm/C; SizeArea_mm2: 1.28; SizeX_mm: 1.6; SizeY_mm: 0.8; U/M: EA; AEC Category: Q200
signal-integrity model Resistor
simulation model Resistor
footprint 0603
footprint 0603M
footprint 0603L
footprint 0603_HV
footprint 0603S
pins: 1, 2

## RC0603FR-07604RL
designator R?  ValueDisplayed: 604  (hidden comment: RC0603FR-07604RL)
RES, 604, 1%, 0.1 W, 0603; Manufacturer: Yageo America; CompType: Resistor; Value: 604; Value_Code: 604R; Tolerance_%: 1; Power_W: 0.1; Value2: 0.1W; VDC_V: 150; TempCo: 200 ppm/C; SizeArea_mm2: 1.28; SizeX_mm: 1.6; SizeY_mm: 0.8; EIA_Code: E96; U/M: EA; AEC Category: Q200; Green_Lifecycle: Active; Green_REACh: Passed
signal-integrity model Resistor
simulation model Resistor
footprint 0603
footprint 0603M
footprint 0603L
footprint 0603_HV
footprint 0603S
pins: 1, 2

## RC0603JR-074K7L
designator R?  ValueDisplayed: 4.7k  (hidden comment: RC0603JR-074K7L)
RES, 4.7 k, 5%, 0.1 W, 0603; Manufacturer: Yageo America; CompType: Resistor; Value: 4.7k; Res_ohm: 4700; Value_Code: 4k70; Tolerance_%: 5; Power_W: 0.1; Value2: 0.1W; VDC_V: 50; TempCo: 100 ppm/C; SizeArea_mm2: 1.28; SizeX_mm: 1.6; SizeY_mm: 0.8; SizeZ_mm: 1; EIA_Code: E24; U/M: EA; AEC Category: Q200; Green_Lifecycle: Active; Green_REACh: Passed
signal-integrity model Resistor
simulation model Resistor
footprint 0603
footprint 0603M
footprint 0603L
footprint 0603_HV
footprint 0603S
pins: 1, 2

## RC0603JR-07270RL
designator R?  ValueDisplayed: 270  (hidden comment: RC0603JR-07270RL)
RES, 270, 5%, 0.1 W, 0603; Manufacturer: Yageo America; CompType: Resistor; Tolerance_%: 5; VDC_V: 50; Power_W: 0.1; Value: 270; U/M: EA; Value_Code: 270R; Value2: 0.1W; EIA_Code: E24; TempCo: 100 ppm/C; SizeArea_mm2: 1.28; SizeX_mm: 1.6; SizeY_mm: 0.8; SizeZ_mm: 1; AEC Category: Q200
signal-integrity model Resistor
simulation model Resistor
footprint 0603
footprint 0603M
footprint 0603L
footprint 0603_HV
footprint 0603S
pins: 1, 2

## RC0603JR-07330RL
designator R?  value 330  (hidden comment: RC0603JR-07330RL)
RES, 330 ohm, 5%, 0.1W, 0603; Manufacturer: Yageo America; CompType: Resistor; Tolerance_%: 5; VDC_V: 50; Power_W: 0.1; U/M: EA; Value_Code: 330R; EIA_Code: E24
signal-integrity model Resistor
simulation model Resistor
footprint 0603
footprint 0603M
footprint 0603L
footprint 0603_HV
pins: 1, 2

## RMK-3-1052+
designator U?
Frequency Multiplier, 50Ω, Output 6600 to 10500 MHz, SMD; Manufacturer: Minicircuits; SizeZ_mm: 4.06; SizeAreaWB_mm2: 82.4145; SizeArea_mm2: 49.9745; SizeX_mm: 7.87; SizeY_mm: 6.35
footprint Minicircuits_TT1224 (SMD, 6-Leads, Body 7.87x6.35mm)
pins: 1 INPUT (in), 2 GND (power), 3 GND (power), 4 OUTPUT (out), 5 GND (power), 6 GND (power)

## RT0603DRE07120RL
designator R?  ValueDisplayed: 120  (hidden comment: RT0603DRE07120RL)
RES, 120, 0.5%, 0.1 W, 0603; Manufacturer: Yageo America; CompType: Resistor; Tolerance_%: 0.5; VDC_V: 75; Power_W: 0.1; Value: 120; U/M: EA; Value_Code: 120R; Value2: 0.1W; TempCo: 50 ppm/C; EIA_Code: E192; SizeArea_mm2: 1.28; SizeX_mm: 1.6; SizeY_mm: 0.8; SizeZ_mm: 1; AEC Category: Q200
signal-integrity model Resistor
simulation model Resistor
footprint 0603
footprint 0603M
footprint 0603L
footprint 0603_HV
footprint 0603S
pins: 1, 2

## Samtec_IP5-04-05.0-X-S-X-TR
designator J?, comment IP5-04-05.0-L-S-1-TR
Plug, 4 Ports, TH; Manufacturer: Samtec; Gender: Male; Voltage_V: 200V; ContactFinish: Gold; Row_Count: 1; Current_A: 2.36A; Cert_UL: Y
footprint Samtec_IP5-04-05.0-X-S-X-TR (Plug, 4 Ports, TH)
pins: P1A, P1B, P1C, P1D, P1E, P2A, P2B, P2C, P2D, P2E, P3A, P3B, P3C, P3D, P3E, P4A, P4B, P4C, P4D, P4E

## SJ-5303 (CLEAR)
designator H?
Bumpon, Hemisphere, 0.44 X 0.20, Clear; Manufacturer: 3M; SymbolCreator: a0412235; Green_Lifecycle: Active; Green_REACh: Passed
footprint Bumpon_SJ5003Transparent

## TFMR_5_TC1-1-13M+
designator T?, comment TC1-1-13M+
RF Transformer; Manufacturer: Mini-Circuits
footprint TFMR_5_150x150_50 (TFMR_5_150X150_50)
footprint TFMR_5_150x150_50
pins: 1 secondary_dot, 2 secondary_ct, 3 secondary, 4 primary, 6 primary_dot

## THT-14-423-10
designator LBL?, comment Size: 0.65" x 0.20 "
Thermal Transfer Printable Labels, 0.650" W x 0.200" H - 10,000 per roll; Manufacturer: Brady; PartNumber: THT-14-423-10; SymbolCreator: a0412235; CompType: Label; Green_Lifecycle: Not Set; Green_REACh: Incomplete
footprint Label_650x200

## TI_Logo
designator Logo?, comment Texas Instruments  (value not drawn)  (no BOM)
Texas Instrument Corporate Signature; SymbolCreator: a0412235
footprint TI_Stacked_SolderMask_Medium
footprint TI_Stacked_SolderMask_Small
footprint TI_Stacked_Overlay_Medium
footprint TI_Stacked_Overlay_Small
footprint TI_Horizontal_SolderMask_Medium
footprint TI_Horizontal_SolderMask_Small
footprint TI_Horizontal_Overlay_Medium
footprint TI_Horizontal_Overlay_Small
footprint TI_Symbol_SolderMask_Small
footprint TI_Symbol_Overlay_Medium
footprint TI_Symbol_Overlay_Small
footprint TI_Symbol_SolderMask_Medium

## TP-025-SMT
designator TP?  (value not drawn)
Test Point, O.025"; Manufacturer: STD; Value: STD
footprint TP_25MIL-SMT
pins: 1

## TSW-102-07-T-S
designator J?  (value not drawn)
Header, 2.54 mm, 2x1, Tin, TH; Manufacturer: Samtec; SymbolCreator: a0412235; Pitch_mm: 2.54; Gender: Male; Shrouded: N; Row_Count: 1; Current_A: 6.3; Voltage_V: 550; Cert_CSA: Y; Green_Lifecycle: Active; Green_REACh: Passed
footprint Samtec_TSW-102-07-T-S
pins: 1, 2
1 alternate drawing of the same symbol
